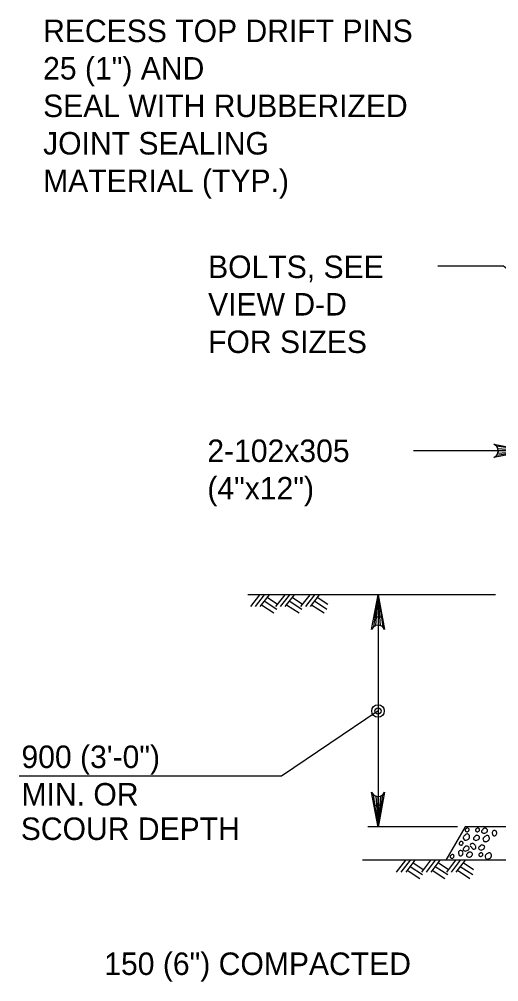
# Model space of a CAD drawing. Extents: x 0 to 36.3, y -44 to 0.
# Drawn here: x 15.9 to 18.45, y -17.83 to -12.69 of the extents above; entities that cross this region are included whole.
import ezdxf

# ---------------------------------------------------------------- set-up
doc = ezdxf.new("R2010")
doc.units = 0
doc.layers.add('3', color=7, linetype='Continuous')
doc.layers.add('5', color=7, linetype='Continuous')

msp = doc.modelspace()

# ---------------------------------------------------------------- linework, layer by layer
at = {"layer": '3'}
for p, q in [((18.4357, -15.7602), (17.1156, -15.7602)), ((17.1788, -15.7602), (17.1299, -15.8238)), ((17.2039, -15.7602), (17.1551, -15.8238)), ((17.2292, -15.7602), (17.1803, -15.8238)), ((17.3126, -15.7602), (17.2638, -15.8238)), ((17.3378, -15.7602), (17.289, -15.8238)), ((17.363, -15.7602), (17.3142, -15.8238)), ((17.4465, -15.7602), (17.3977, -15.8238)), ((17.4717, -15.7602), (17.4228, -15.8238)), ((17.4969, -15.7602), (17.4481, -15.8238)), ((17.1882, -15.8136), (17.2551, -15.8576)), ((17.2035, -15.7936), (17.2705, -15.8376)), ((17.2189, -15.7735), (17.2744, -15.81)), ((17.322, -15.8136), (17.389, -15.8576)), ((17.3374, -15.7936), (17.4043, -15.8376)), ((17.3528, -15.7735), (17.4082, -15.81)), ((17.4559, -15.8136), (17.5228, -15.8576)), ((17.4712, -15.7936), (17.5382, -15.8376)), ((17.4867, -15.7735), (17.5422, -15.81)), ((18.2742, -16.9987), (18.172, -17.1758)), ((22.2309, -16.9987), (18.2742, -16.9987)), ((22.7392, -17.1758), (17.728, -17.1758)), ((17.9561, -17.1758), (17.9072, -17.2395)), ((17.9812, -17.1758), (17.9325, -17.2395)), ((18.0065, -17.1758), (17.9577, -17.2395)), ((17.9962, -17.1892), (18.0517, -17.2257)), ((18.09, -17.1758), (18.0412, -17.2395)), ((18.1152, -17.1758), (18.0663, -17.2395)), ((18.1403, -17.1758), (18.0915, -17.2395)), ((18.1301, -17.1892), (18.1856, -17.2257)), ((18.2238, -17.1758), (18.175, -17.2395)), ((18.249, -17.1758), (18.2003, -17.2395)), ((18.2742, -17.1758), (18.2254, -17.2395)), ((18.264, -17.1892), (18.3195, -17.2257)), ((17.9655, -17.2293), (18.0325, -17.2733)), ((17.9808, -17.2093), (18.0478, -17.2532)), ((18.0993, -17.2293), (18.1663, -17.2733)), ((18.1148, -17.2093), (18.1817, -17.2532)), ((18.2332, -17.2293), (18.3002, -17.2733)), ((18.2486, -17.2093), (18.3156, -17.2532))]:
    msp.add_line(p, q, dxfattribs=at)
for centre, radius, start, end in [((18.2985, -17.0742), 0.0401, 127.3314, 141.3377), ((18.3041, -17.0815), 0.0493, 118.2986, 127.3314), ((18.2823, -17.0155), 0.0075, 146.3076, 194.0029), ((18.2839, -17.0151), 0.00917, 194.0029, 221.1884), ((18.2833, -17.0162), 0.00871, 102.2565, 146.3076), ((18.2844, -17.0146), 0.0099, 221.1884, 247.3407), ((18.2874, -17.014), 0.00935, 97.1244, 143.8595), ((18.285, -17.0132), 0.0114, 247.3407, 278.1294), ((18.2875, -17.0507), 0.0143, 101.4986, 118.2986), ((18.2867, -17.0467), 0.0102, 68.9642, 101.4986), ((18.2872, -17.0126), 0.00794, 46.1387, 97.1244), ((18.2852, -17.0143), 0.0104, 278.1294, 310.4731), ((18.2865, -17.0473), 0.0109, 37.4711, 68.9642), ((18.284, -17.0129), 0.0121, 310.4731, 335.5541), ((18.2847, -17.0152), 0.0116, 26.5671, 46.1387), ((18.2875, -17.0138), 0.00848, 3.6256, 26.5671), ((18.2862, -17.0139), 0.00973, 335.5541, 3.6256), ((18.2838, -17.0493), 0.0143, 18.4365, 37.4711), ((18.2784, -17.0511), 0.0199, 2.3392, 18.4365), ((18.3385, -17.0566), 0.014, 140.7081, 167.2711), ((18.3353, -17.054), 0.00984, 108.9149, 140.7081), ((18.3378, -17.0155), 0.0075, 146.3076, 194.0029), ((18.3394, -17.0151), 0.00917, 194.0029, 221.1884), ((18.3388, -17.0162), 0.00871, 102.2565, 146.3076), ((18.3371, -17.0593), 0.0155, 90, 108.9149), ((18.34, -17.0146), 0.0099, 221.1884, 247.3407), ((18.3429, -17.014), 0.00935, 97.1244, 143.8595), ((18.3405, -17.0132), 0.0114, 247.3407, 278.1294), ((18.3371, -17.062), 0.0182, 72.5511, 90), ((18.3427, -17.0126), 0.00794, 46.1387, 97.1244), ((18.3407, -17.0143), 0.0104, 278.1294, 310.4731), ((18.338, -17.0593), 0.0153, 47.7288, 72.5511), ((18.3395, -17.0129), 0.0121, 310.4731, 335.5541), ((18.3402, -17.0152), 0.0116, 26.5671, 46.1387), ((18.3405, -17.0565), 0.0115, 19.08, 47.7288), ((18.343, -17.0138), 0.00848, 3.6256, 26.5671), ((18.3417, -17.0139), 0.00973, 335.5541, 3.6256), ((18.3693, -17.0227), 0.00747, 143.9702, 187.7584), ((18.3691, -17.0228), 0.00724, 187.7584, 225.0025), ((18.3706, -17.0237), 0.00907, 104.4085, 143.9702), ((18.3762, -17.0156), 0.0173, 225.0025, 248.8171), ((18.3812, -17.0188), 0.014, 140.7081, 167.2711), ((18.3758, -17.0168), 0.0161, 248.8171, 282.2637), ((18.378, -17.0162), 0.00984, 108.9149, 140.7081), ((18.3798, -17.0215), 0.0155, 90, 108.9149), ((18.3749, -17.0127), 0.0203, 282.2637, 311.9318), ((18.4095, -17.0895), 0.0493, 118.2986, 127.3314), ((18.3798, -17.0242), 0.0182, 72.5511, 90), ((18.3806, -17.0215), 0.0153, 47.7288, 72.5511), ((18.3929, -17.0587), 0.0143, 101.4986, 118.2986), ((18.3738, -17.0115), 0.0219, 311.9318, 336.3688), ((18.3921, -17.0547), 0.0102, 68.9642, 101.4986), ((18.3832, -17.0187), 0.0115, 19.08, 47.7288), ((18.3871, -17.0173), 0.00738, 336.3688, 19.08), ((18.3919, -17.0553), 0.0109, 37.4711, 68.9642), ((18.4292, -17.0295), 0.0106, 134.9029, 173.2896), ((18.431, -17.0297), 0.0124, 173.2896, 208.6507), ((18.4317, -17.0358), 0.0117, 187.256, 209.0568), ((18.43, -17.0367), 0.00977, 209.0568, 232.9021), ((18.4312, -17.0316), 0.0135, 104.0351, 134.9029), ((18.4324, -17.0336), 0.0137, 232.9021, 246.8032), ((18.431, -17.0368), 0.0102, 246.8032, 262.9077), ((18.4307, -17.0295), 0.0114, 70.3851, 104.0351), ((18.4305, -17.0408), 0.00621, 262.9077, 300.2542), ((18.4224, -17.0269), 0.0222, 300.2542, 319.7493), ((18.43, -17.0317), 0.0137, 45.0025, 70.3851), ((18.4266, -17.0305), 0.0167, 319.7493, 347.4701), ((18.4311, -17.0305), 0.0121, 17.9593, 45.0025), ((18.4294, -17.0311), 0.0139, 347.4701, 17.9593), ((18.2501, -17.0871), 0.0075, 146.3076, 194.0029), ((18.2517, -17.0867), 0.00917, 194.0029, 221.1884), ((18.2511, -17.0878), 0.00871, 102.2565, 146.3076), ((18.2523, -17.0862), 0.0099, 221.1884, 247.3407), ((18.2552, -17.0856), 0.00935, 97.1244, 143.8595), ((18.2528, -17.0848), 0.0114, 247.3407, 278.1294), ((18.255, -17.0842), 0.00794, 46.1387, 97.1244), ((18.253, -17.0859), 0.0104, 278.1294, 310.4731), ((18.2518, -17.0845), 0.0121, 310.4731, 335.5541), ((18.2525, -17.0868), 0.0116, 26.5671, 46.1387), ((18.2553, -17.0854), 0.00848, 3.6256, 26.5671), ((18.254, -17.0855), 0.00973, 335.5541, 3.6256), ((18.2699, -17.0558), 0.00558, 164.7784, 205.3396), ((18.2785, -17.0581), 0.0144, 141.3377, 164.7784), ((18.2787, -17.0516), 0.0153, 205.3396, 229.5229), ((18.2797, -17.0584), 0.0139, 203.6387, 219.8081), ((18.2733, -17.0638), 0.00552, 219.8081, 245.6186), ((18.2754, -17.0591), 0.0106, 245.6186, 273.3662), ((18.2741, -17.0379), 0.0319, 273.3662, 289.2839), ((18.2724, -17.0331), 0.037, 289.2839, 302.7329), ((18.2861, -17.0543), 0.0118, 302.7329, 326.7251), ((18.2848, -17.0535), 0.0133, 326.7251, 347.0043), ((18.2752, -17.0513), 0.0232, 347.0043, 2.3392), ((18.3152, -17.1007), 0.0146, 129.47, 171.7294), ((18.3123, -17.0972), 0.0101, 77.9637, 129.47), ((18.3092, -17.112), 0.0253, 65.558, 77.9637), ((18.3267, -17.0606), 0.00747, 143.9702, 187.7584), ((18.3264, -17.0606), 0.00724, 187.7584, 225.0025), ((18.313, -17.1035), 0.0159, 49.9215, 65.558), ((18.3279, -17.0615), 0.00907, 104.4085, 143.9702), ((18.3336, -17.0535), 0.0173, 225.0025, 248.8171), ((18.3049, -17.1131), 0.0285, 35.5401, 49.9215), ((18.3331, -17.0546), 0.0161, 248.8171, 282.2637), ((18.3069, -17.1117), 0.0261, 20.509, 35.5401), ((18.3322, -17.0505), 0.0203, 282.2637, 311.9318), ((18.3312, -17.0493), 0.0219, 311.9318, 336.3688), ((18.3445, -17.0551), 0.00738, 336.3688, 19.08), ((18.3659, -17.1081), 0.014, 140.7081, 167.2711), ((18.3627, -17.1055), 0.00984, 108.9149, 140.7081), ((18.3645, -17.1108), 0.0155, 90, 108.9149), ((18.3645, -17.1135), 0.0182, 72.5511, 90), ((18.3753, -17.0638), 0.00558, 164.7784, 205.3396), ((18.3839, -17.0662), 0.0144, 141.3377, 164.7784), ((18.3654, -17.1108), 0.0153, 47.7288, 72.5511), ((18.3841, -17.0597), 0.0153, 205.3396, 229.5229), ((18.3851, -17.0664), 0.0139, 203.6387, 219.8081), ((18.4039, -17.0822), 0.0401, 127.3314, 141.3377), ((18.3787, -17.0718), 0.00552, 219.8081, 245.6186), ((18.3679, -17.108), 0.0115, 19.08, 47.7288), ((18.3808, -17.0672), 0.0106, 245.6186, 273.3662), ((18.3795, -17.0459), 0.0319, 273.3662, 289.2839), ((18.3778, -17.0411), 0.037, 289.2839, 302.7329), ((18.3915, -17.0624), 0.0118, 302.7329, 326.7251), ((18.3892, -17.0574), 0.0143, 18.4365, 37.4711), ((18.3902, -17.0615), 0.0133, 326.7251, 347.0043), ((18.3838, -17.0592), 0.0199, 2.3392, 18.4365), ((18.3806, -17.0593), 0.0232, 347.0043, 2.3392), ((18.2028, -17.1578), 0.00871, 102.2565, 146.3076), ((18.2069, -17.1556), 0.00935, 97.1244, 143.8595), ((18.2067, -17.1542), 0.00794, 46.1387, 97.1244), ((18.2042, -17.1568), 0.0116, 26.5671, 46.1387), ((18.2513, -17.1369), 0.0124, 173.2896, 208.6507), ((18.2495, -17.1367), 0.0106, 134.9029, 173.2896), ((18.252, -17.143), 0.0117, 187.256, 209.0568), ((18.2503, -17.1439), 0.00977, 209.0568, 232.9021), ((18.2516, -17.1387), 0.0135, 104.0351, 134.9029), ((18.251, -17.1367), 0.0114, 70.3851, 104.0351), ((18.2428, -17.1341), 0.0222, 300.2542, 319.7493), ((18.2503, -17.1388), 0.0137, 45.0025, 70.3851), ((18.2469, -17.1376), 0.0167, 319.7493, 347.4701), ((18.2514, -17.1377), 0.0121, 17.9593, 45.0025), ((18.2497, -17.1383), 0.0139, 347.4701, 17.9593), ((18.2711, -17.1177), 0.00747, 143.9702, 187.7584), ((18.2709, -17.1177), 0.00724, 187.7584, 225.0025), ((18.2724, -17.1186), 0.00907, 104.4085, 143.9702), ((18.278, -17.1106), 0.0173, 225.0025, 248.8171), ((18.283, -17.1137), 0.014, 140.7081, 167.2711), ((18.2776, -17.1117), 0.0161, 248.8171, 282.2637), ((18.2798, -17.1111), 0.00984, 108.9149, 140.7081), ((18.2816, -17.1164), 0.0155, 90, 108.9149), ((18.2767, -17.1076), 0.0203, 282.2637, 311.9318), ((18.2888, -17.1499), 0.00747, 143.9702, 187.7584), ((18.2886, -17.1499), 0.00724, 187.7584, 225.0025), ((18.2816, -17.1191), 0.0182, 72.5511, 90), ((18.2901, -17.1508), 0.00907, 104.4085, 143.9702), ((18.2825, -17.1164), 0.0153, 47.7288, 72.5511), ((18.3007, -17.1459), 0.014, 140.7081, 167.2711), ((18.2975, -17.1433), 0.00984, 108.9149, 140.7081), ((18.2757, -17.1065), 0.0219, 311.9318, 336.3688), ((18.285, -17.1136), 0.0115, 19.08, 47.7288), ((18.2993, -17.1486), 0.0155, 90, 108.9149), ((18.2889, -17.1123), 0.00738, 336.3688, 19.08), ((18.2993, -17.1513), 0.0182, 72.5511, 90), ((18.2542, -17.157), 0.0734, 45.0025, 49.7663), ((18.3002, -17.1486), 0.0153, 47.7288, 72.5511), ((18.267, -17.1442), 0.0552, 39.5094, 45.0025), ((18.2934, -17.1386), 0.0219, 311.9318, 336.3688), ((18.2778, -17.1352), 0.0412, 32.5518, 39.5094), ((18.3027, -17.1458), 0.0115, 19.08, 47.7288), ((18.3255, -17.1048), 0.0154, 212.5518, 223.9474), ((18.3066, -17.1444), 0.00738, 336.3688, 19.08), ((18.3178, -17.1123), 0.00464, 223.9474, 259.696), ((18.3211, -17.0942), 0.023, 259.696, 275.5269), ((18.3219, -17.1024), 0.0147, 275.5269, 296.563), ((18.3251, -17.1089), 0.00751, 296.563, 326.1765), ((18.3138, -17.1092), 0.0187, 0, 20.509), ((18.3255, -17.1092), 0.00701, 326.1765, 0), ((18.354, -17.1121), 0.00747, 143.9702, 187.7584), ((18.3538, -17.1121), 0.00724, 187.7584, 225.0025), ((18.3553, -17.113), 0.00907, 104.4085, 143.9702), ((18.3555, -17.1475), 0.0075, 146.3076, 194.0029), ((18.3571, -17.147), 0.00917, 194.0029, 221.1884), ((18.3609, -17.1049), 0.0173, 225.0025, 248.8171), ((18.3565, -17.1481), 0.00871, 102.2565, 146.3076), ((18.3606, -17.1459), 0.00935, 97.1244, 143.8595), ((18.3605, -17.1061), 0.0161, 248.8171, 282.2637), ((18.3604, -17.1445), 0.00794, 46.1387, 97.1244), ((18.3596, -17.102), 0.0203, 282.2637, 311.9318), ((18.3572, -17.1449), 0.0121, 310.4731, 335.5541), ((18.3579, -17.1472), 0.0116, 26.5671, 46.1387), ((18.3607, -17.1458), 0.00848, 3.6256, 26.5671), ((18.3594, -17.1459), 0.00973, 335.5541, 3.6256), ((18.3586, -17.1008), 0.0219, 311.9318, 336.3688), ((18.3718, -17.1066), 0.00738, 336.3688, 19.08), ((18.3949, -17.159), 0.0144, 141.3377, 164.7784), ((18.4149, -17.175), 0.0401, 127.3314, 141.3377), ((18.4205, -17.1824), 0.0493, 118.2986, 127.3314), ((18.4039, -17.1516), 0.0143, 101.4986, 118.2986), ((18.4031, -17.1476), 0.0102, 68.9642, 101.4986), ((18.4029, -17.1482), 0.0109, 37.4711, 68.9642), ((18.4002, -17.1502), 0.0143, 18.4365, 37.4711), ((18.3948, -17.152), 0.0199, 2.3392, 18.4365), ((18.2018, -17.1571), 0.0075, 146.3076, 194.0029), ((18.2034, -17.1567), 0.00917, 194.0029, 221.1884), ((18.204, -17.1562), 0.0099, 221.1884, 247.3407), ((18.2046, -17.1548), 0.0114, 247.3407, 278.1294), ((18.2047, -17.1559), 0.0104, 278.1294, 310.4731), ((18.2036, -17.1545), 0.0121, 310.4731, 335.5541), ((18.207, -17.1554), 0.00848, 3.6256, 26.5671), ((18.2057, -17.1555), 0.00973, 335.5541, 3.6256), ((18.2527, -17.1408), 0.0137, 232.9021, 246.8032), ((18.2513, -17.1439), 0.0102, 246.8032, 262.9077), ((18.2508, -17.1479), 0.00621, 262.9077, 300.2542), ((18.2957, -17.1428), 0.0173, 225.0025, 248.8171), ((18.2953, -17.1439), 0.0161, 248.8171, 282.2637), ((18.2944, -17.1398), 0.0203, 282.2637, 311.9318), ((18.3577, -17.1466), 0.0099, 221.1884, 247.3407), ((18.3582, -17.1452), 0.0114, 247.3407, 278.1294), ((18.3584, -17.1462), 0.0104, 278.1294, 310.4731), ((18.3863, -17.1567), 0.00558, 164.7784, 205.3396), ((18.3951, -17.1525), 0.0153, 205.3396, 229.5229), ((18.3961, -17.1593), 0.0139, 203.6387, 219.8081), ((18.3897, -17.1647), 0.00552, 219.8081, 245.6186), ((18.3918, -17.16), 0.0106, 245.6186, 273.3662), ((18.3905, -17.1388), 0.0319, 273.3662, 289.2839), ((18.3888, -17.1339), 0.037, 289.2839, 302.7329), ((18.4025, -17.1552), 0.0118, 302.7329, 326.7251), ((18.4012, -17.1544), 0.0133, 326.7251, 347.0043), ((18.3916, -17.1521), 0.0232, 347.0043, 2.3392)]:
    msp.add_arc(centre, radius, start, end, dxfattribs=at)
at = {"layer": '5'}
for p, q in [((17.8103, -15.7602), (17.8103, -17.0003)), ((17.8103, -16.3803), (17.2956, -16.7287)), ((17.2956, -16.7287), (15.8977, -16.7287)), ((18.2341, -16.9987), (17.7562, -16.9987))]:
    msp.add_line(p, q, dxfattribs=at)
for points in [[(18.7454, -14.2215), (18.4798, -14.0069), (18.1295, -14.0069)], [(18.6138, -14.9922), (17.9997, -14.9922)], [(18.6138, -14.9923), (18.4274, -15.0272), (18.4417, -15.0172), (18.4492, -15.0047), (18.4513, -14.9923), (18.4492, -14.9797), (18.4417, -14.9672), (18.4274, -14.9573), (18.6138, -14.9923), (18.4417, -14.9672), (18.4492, -14.9797), (18.6138, -14.9923), (18.4513, -14.9923), (18.4492, -15.0047), (18.6138, -14.9923), (18.4417, -15.0172)], [(17.8103, -15.7602), (17.8453, -15.9466), (17.8353, -15.9322), (17.8228, -15.9248), (17.8103, -15.9227), (17.7978, -15.9248), (17.7853, -15.9322), (17.7754, -15.9466), (17.8103, -15.7602), (17.7853, -15.9322), (17.7978, -15.9248), (17.8103, -15.7602), (17.8103, -15.9227), (17.8228, -15.9248), (17.8103, -15.7602), (17.8353, -15.9322)], [(17.8103, -17.0003), (17.7754, -16.8139), (17.7853, -16.8283), (17.7978, -16.8357), (17.8103, -16.8378), (17.8228, -16.8357), (17.8353, -16.8283), (17.8453, -16.8139), (17.8103, -17.0003), (17.8353, -16.8283), (17.8228, -16.8357), (17.8103, -17.0003), (17.8103, -16.8378), (17.7978, -16.8357), (17.8103, -17.0003), (17.7853, -16.8283)]]:
    msp.add_lwpolyline(points, dxfattribs=at)
for points in [[(17.7907, -15.8782), (17.83, -15.8782), (17.8103, -15.7602)], [(17.7907, -16.8822), (17.83, -16.8822), (17.8103, -17.0003)]]:
    msp.add_lwpolyline(points, close=True, dxfattribs=at)
for radius in [0.0333, 0.0167]:
    msp.add_circle((17.8103, -16.3802), radius, dxfattribs=at)

# ---------------------------------------------------------------- texts
for s, p in [('RECESS TOP DRIFT PINS', (16.0248, -12.8117)), ('25 (1") AND', (16.0248, -13.0117)), ('SEAL WITH RUBBERIZED', (16.0248, -13.2118)), ('JOINT SEALING', (16.0248, -13.4117)), ('MATERIAL (TYP.)', (16.0248, -13.6117)), ('BOLTS, SEE', (16.9043, -14.0706)), ('VIEW D-D', (16.9043, -14.2706)), ('FOR SIZES', (16.9043, -14.4706)), ('2-102x305', (16.9003, -15.0521)), ('(4"x12")', (16.9003, -15.2521)), ('900 (3\'-0")', (15.9094, -16.6848)), ('MIN. OR', (15.9094, -16.8848)), ('SCOUR DEPTH', (15.9057, -17.0687)), ('150 (6") COMPACTED', (16.3508, -17.7889))]:
    msp.add_text(s, height=0.12, dxfattribs=at).set_placement(p)

doc.saveas('drawing.dxf')
